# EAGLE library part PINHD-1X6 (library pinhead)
PIN HEADER
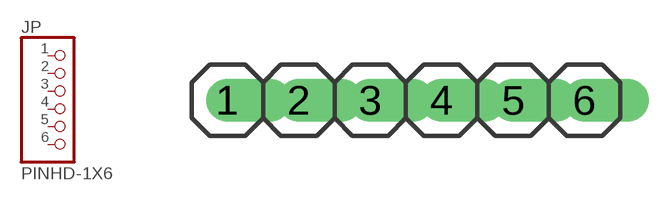
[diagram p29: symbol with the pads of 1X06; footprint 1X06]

Designator prefix JP

## PINHD-1X6  [1X06]
1  1  pas
2  2  pas
3  3  pas
4  4  pas
5  5  pas
6  6  pas

## Footprint 1X06 (pad centres in mm)
PIN HEADER
drill 1.016 offset: 1 -6.35,0; 2 -3.81,0; 3 -1.27,0; 4 1.27,0; 5 3.81,0; 6 6.35,0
